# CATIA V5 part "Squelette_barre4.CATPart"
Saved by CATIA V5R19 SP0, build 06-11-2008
Part number: Squelette_barre4
Bounding box of the stored display mesh (mm): x 0 to 25, y 0 to 20, z 0 to 5
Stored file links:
  F:\IAO\Catia\Squelette_barre4.CATPart
  F:\IAO\Catia\Etau.CATProduct
  F:\IAO\Catia\Base.CATPart
  F:\IAO\Catia\Squelette_pivot.CATPart
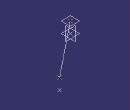
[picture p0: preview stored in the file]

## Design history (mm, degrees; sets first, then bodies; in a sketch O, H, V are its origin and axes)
Set1
  Point1: linked copy from another document
  Point2: linked copy from another document
Body1 (main body)
  Point3: (0, 0, 5), relative to Point1
  Point4: (0, 0, 5), relative to Point2
  Line1: type PtPt, SecondPoint Point4, FirstPoint Point3
  Plane1: type Offset, Offset 5, RefPlane xy-plane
